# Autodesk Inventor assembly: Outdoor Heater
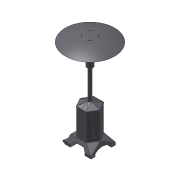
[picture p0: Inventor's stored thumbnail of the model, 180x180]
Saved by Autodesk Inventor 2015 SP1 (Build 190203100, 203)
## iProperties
Category: Mechanical Engineering Drawing and Design - CADD
Manager: Fábio Ricardo de Oliveira Souza
Company: SENAI - Serviço Nacional de Aprendizagem Industrial
Created: 2011-06
Part Number: Outdoor Heater
Document SubType Name: Assembly
Designer: Guilherme Augusto Franco de Souza
Engineer: George Geraldo de Oliveia Silva
Authority: Fábio Ricardo de Oliveira Soza
Subject: WorldSkill 2011 - London, England
Author: Guilherme Augusto Franco de Souza
Revision Number: 00
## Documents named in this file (8)
- E:\Visitor Experience Project\WSI2015 - Visitor Experience Project\#46- Sheet Metal Technology\01- 3D Models\Outodoor Heater\2- Assemblies\Outdoor Heater.iam
- E:\Visitor Experience Project\WSI2015 - Visitor Experience Project\#46- Sheet Metal Technology\01- 3D Models\Outodoor Heater\2- Assemblies\Base.iam
- E:\Visitor Experience Project\WSI2015 - Visitor Experience Project\#46- Sheet Metal Technology\01- 3D Models\Outodoor Heater\2- Assemblies\Central body.iam
- E:\Visitor Experience Project\WSI2015 - Visitor Experience Project\#46- Sheet Metal Technology\01- 3D Models\Outodoor Heater\2- Assemblies\Frame.iam
- E:\Visitor Experience Project\WSI2015 - Visitor Experience Project\#46- Sheet Metal Technology\01- 3D Models\Outodoor Heater\2- Assemblies\Outdoor Heater\Design Accelerator\Bolted Connection1.iam
- E:\Visitor Experience Project\WSI2015 - Visitor Experience Project\#46- Sheet Metal Technology\01- 3D Models\Outodoor Heater\2- Assemblies\Neck.iam
- E:\Visitor Experience Project\WSI2015 - Visitor Experience Project\#46- Sheet Metal Technology\01- 3D Models\Outodoor Heater\2- Assemblies\Outdoor Heater\Design Accelerator\Bolted Connection2.iam
- E:\Visitor Experience Project\WSI2015 - Visitor Experience Project\#46- Sheet Metal Technology\01- 3D Models\Outodoor Heater\2- Assemblies\Burner.iam
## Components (7 placed, 6 different names)
1. Base:1 [sub-assembly] — Mate:1, Mate:2, Mate:3, Mate:6, Mate:7, Flush:1, Mate:9, Flush:2, Angle:1, Mate:17
2. Central body:1 [sub-assembly] — Mate:6, Mate:7, Flush:1
3. Frame:1 [sub-assembly] — Mate:1, Mate:2, Mate:3, Mate:8, Mate:16
4. Bolted Connection:1 [sub-assembly] — Mate:16, Mate:17
5. Neck:1 [sub-assembly] — Mate:8, Mate:9, Flush:2, Insert:1, Mate:14, Mate:15
6. Bolted Connection:2 [sub-assembly] — Mate:14, Mate:15
7. Burner:1 [sub-assembly] — Insert:1, Angle:1
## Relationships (15: Mate 11, Flush 2, Insert 1, Angle 1)
- Mate:1: Base:1 ↔ Frame:1
- Mate:2: Base:1 ↔ Frame:1
- Mate:3: Base:1 ↔ Frame:1
- Mate:6: Base:1 ↔ Central body:1
- Mate:7: Base:1 ↔ Central body:1
- Flush:1: Base:1 ↔ Central body:1
- Mate:8: Frame:1 ↔ Neck:1
- Mate:9: Base:1 ↔ Neck:1
- Flush:2: Base:1 ↔ Neck:1
- Insert:1: Neck:1 ↔ Burner:1
- Angle:1: Base:1 ↔ Burner:1
- Mate:14: Neck:1 ↔ Bolted Connection:2
- Mate:15: Neck:1 ↔ Bolted Connection:2
- Mate:16: Frame:1 ↔ Bolted Connection:1
- Mate:17: Base:1 ↔ Bolted Connection:1
